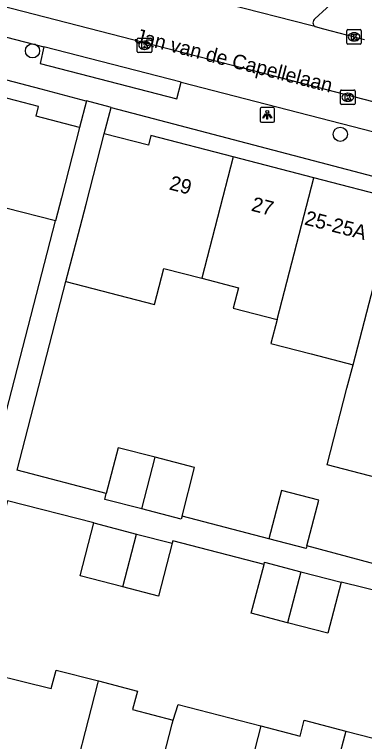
# Model space of a CAD drawing. Extents: x 163686 to 164493, y 382719 to 383870.
# Drawn here: x 164121.7 to 164145.7, y 383167.2 to 383217.3 of the extents above; entities that cross this region are included whole.
import ezdxf

# ---------------------------------------------------------------- set-up
doc = ezdxf.new("R2010")
doc.units = 0
for name, color, linetype in [('IMGEO_Boom', 7, 'Continuous'), ('IMGEO_Kolk', 7, 'Continuous'), ('IMGEO_Lichtpunt', 7, 'Continuous'), ('IMGEO_Openbare_ruimte_label', 7, 'Continuous'), ('IMGEO_Pand', 7, 'Continuous'), ('IMGEO_Pand_nummerreeks', 7, 'Continuous'), ('IMGEO_Rijbaan_lokaal_open', 7, 'Continuous'), ('IMGEO_Voetpad_open', 7, 'Continuous')]:
    doc.layers.add(name, color=color, linetype=linetype)

msp = doc.modelspace()

# ---------------------------------------------------------------- linework, layer by layer
at = {"layer": 'IMGEO_Boom'}
for centre in [(164122.893, 383214.805), (164144.081, 383209.057)]:
    msp.add_circle(centre, 0.489, dxfattribs=at)
at = {"layer": 'IMGEO_Kolk'}
for p, q in [((164144.528, 383215.338), (164144.528, 383216.19)), ((164144.603, 383216.264), (164145.455, 383216.264)), ((164145.529, 383216.19), (164145.529, 383215.338)), ((164130.182, 383215.685), (164131.034, 383215.685)), ((164145.016, 383216.044), (164145.041, 383216.044)), ((164130.107, 383214.759), (164130.107, 383215.611)), ((164130.595, 383215.465), (164130.62, 383215.465)), ((164131.108, 383215.611), (164131.108, 383214.759)), ((164145.455, 383215.264), (164144.603, 383215.264)), ((164145.039, 383215.484), (164145.014, 383215.484)), ((164131.034, 383214.685), (164130.182, 383214.685)), ((164130.618, 383214.905), (164130.593, 383214.905)), ((164144.094, 383211.181), (164144.094, 383212.033)), ((164144.169, 383212.107), (164145.021, 383212.107)), ((164144.582, 383211.887), (164144.607, 383211.887)), ((164145.095, 383212.033), (164145.095, 383211.181)), ((164144.605, 383211.327), (164144.58, 383211.327)), ((164145.021, 383211.107), (164144.169, 383211.107))]:
    msp.add_line(p, q, dxfattribs=at)
for points in [[(164144.528, 383215.338), (164144.528, 383216.19)], [(164144.603, 383216.264), (164145.455, 383216.264)], [(164145.529, 383216.19), (164145.529, 383215.338)], [(164130.182, 383215.685), (164131.034, 383215.685)], [(164144.849, 383215.964), (164144.972, 383215.964), (164144.972, 383215.813), (164145.102, 383215.964), (164145.266, 383215.964), (164145.12, 383215.813), (164145.273, 383215.564), (164145.121, 383215.564), (164145.036, 383215.728), (164144.972, 383215.661), (164144.972, 383215.564), (164144.849, 383215.564), (164144.849, 383215.964)], [(164130.107, 383214.759), (164130.107, 383215.611)], [(164130.428, 383215.385), (164130.551, 383215.385), (164130.551, 383215.234), (164130.681, 383215.385), (164130.845, 383215.385), (164130.699, 383215.234), (164130.852, 383214.985), (164130.7, 383214.985), (164130.615, 383215.149), (164130.551, 383215.082), (164130.551, 383214.985), (164130.428, 383214.985), (164130.428, 383215.385)], [(164131.108, 383215.611), (164131.108, 383214.759)], [(164145.455, 383215.264), (164144.603, 383215.264)], [(164131.034, 383214.685), (164130.182, 383214.685)], [(164144.094, 383211.181), (164144.094, 383212.033)], [(164144.169, 383212.107), (164145.021, 383212.107)], [(164144.415, 383211.807), (164144.538, 383211.807), (164144.538, 383211.656), (164144.668, 383211.807), (164144.832, 383211.807), (164144.686, 383211.656), (164144.839, 383211.407), (164144.687, 383211.407), (164144.602, 383211.571), (164144.538, 383211.504), (164144.538, 383211.407), (164144.415, 383211.407), (164144.415, 383211.807)], [(164145.095, 383212.033), (164145.095, 383211.181)], [(164145.021, 383211.107), (164144.169, 383211.107)]]:
    msp.add_lwpolyline(points, dxfattribs=at)
for centre, start, end in [((164144.605, 383216.188), 91.552, 178.448), ((164144.605, 383216.188), 91.552, 178.448), ((164145.453, 383216.188), 1.552, 88.448), ((164145.453, 383216.188), 1.552, 88.448), ((164130.184, 383215.609), 91.552, 178.448), ((164130.184, 383215.609), 91.552, 178.448), ((164131.032, 383215.609), 1.552, 88.448), ((164131.032, 383215.609), 1.552, 88.448), ((164144.605, 383215.34), 181.552, 268.448), ((164144.605, 383215.34), 181.552, 268.448), ((164145.453, 383215.34), 271.552, 358.448), ((164145.453, 383215.34), 271.552, 358.448), ((164130.184, 383214.761), 181.552, 268.448), ((164130.184, 383214.761), 181.552, 268.448), ((164131.032, 383214.761), 271.552, 358.448), ((164131.032, 383214.761), 271.552, 358.448), ((164144.171, 383212.031), 91.552, 178.448), ((164144.171, 383212.031), 91.552, 178.448), ((164145.019, 383212.031), 1.552, 88.448), ((164145.019, 383212.031), 1.552, 88.448), ((164144.171, 383211.183), 181.552, 268.448), ((164144.171, 383211.183), 181.552, 268.448), ((164145.019, 383211.183), 271.552, 358.448), ((164145.019, 383211.183), 271.552, 358.448)]:
    msp.add_arc(centre, 0.0765, start, end, dxfattribs=at)
for centre, major_axis, ratio, start_param, end_param in [((164145.015, 383215.764), (-0.387, 0.002), 0.722429, 4.712389, 7.853982), ((164145.04, 383215.764), (-0.39, 0.002), 0.717154, 1.570796, 4.712389), ((164130.594, 383215.185), (-0.387, 0.002), 0.722429, 4.712389, 7.853982), ((164130.619, 383215.185), (-0.39, 0.002), 0.717154, 1.570796, 4.712389), ((164144.581, 383211.607), (-0.387, 0.002), 0.722429, 4.712389, 7.853982), ((164144.606, 383211.607), (-0.39, 0.002), 0.717154, 1.570796, 4.712389)]:
    msp.add_ellipse(centre, major_axis=major_axis, ratio=ratio, start_param=start_param, end_param=end_param, dxfattribs=at)
at = {"layer": 'IMGEO_Lichtpunt'}
for p, q in [((164138.558, 383210.8), (164138.558, 383209.993)), ((164138.558, 383210.8), (164138.558, 383209.993)), ((164139.46, 383210.895), (164138.652, 383210.895)), ((164139.46, 383210.895), (164138.652, 383210.895)), ((164139.554, 383209.993), (164139.554, 383210.8)), ((164139.554, 383209.993), (164139.554, 383210.8)), ((164138.652, 383209.899), (164139.46, 383209.899)), ((164138.652, 383209.899), (164139.46, 383209.899))]:
    msp.add_line(p, q, dxfattribs=at)
for points in [[(164138.932, 383210.464), (164138.971, 383210.436), (164138.783, 383210.174), (164138.745, 383210.201), (164138.932, 383210.464)], [(164139.034, 383210.416), (164139.081, 383210.416), (164139.081, 383210.094), (164139.034, 383210.094), (164139.034, 383210.416)], [(164139.144, 383210.436), (164139.182, 383210.463), (164139.369, 383210.201), (164139.33, 383210.173), (164139.144, 383210.436)]]:
    msp.add_lwpolyline(points, dxfattribs=at)
msp.add_circle((164139.057, 383210.598), 0.0994, dxfattribs=at)
for centre, start, end in [((164138.652, 383210.8), 90, 180), ((164138.652, 383210.8), 90, 180), ((164139.46, 383210.8), 0, 90), ((164139.46, 383210.8), 0, 90), ((164138.652, 383209.993), 180, 270), ((164138.652, 383209.993), 180, 270), ((164139.46, 383209.993), 270, 0), ((164139.46, 383209.993), 270, 360)]:
    msp.add_arc(centre, 0.0946, start, end, dxfattribs=at)
at = {"layer": 'IMGEO_Pand'}
for points in [[(164126.14, 383209.527), (164123.14, 383210.305), (164123.312, 383210.967), (164117.47, 383212.48)], [(164126.14, 383209.527), (164124.885, 383204.688), (164124.471, 383203.091)], [(164125.201, 383198.919), (164126.168, 383202.651), (164126.583, 383204.249), (164127.838, 383209.088)], [(164136.711, 383207.499), (164131.051, 383208.967), (164130.878, 383208.299), (164127.838, 383209.088)], [(164136.711, 383207.499), (164134.545, 383199.144)], [(164142.264, 383206.059), (164136.711, 383207.499)], [(164139.734, 383196.302), (164142.264, 383206.059)], [(164147.926, 383204.591), (164142.264, 383206.059)], [(164144.962, 383193.187), (164147.926, 383204.591)], [(164124.471, 383203.091), (164121.059, 383203.975), (164120.74, 383202.742), (164118.128, 383203.418), (164115.309, 383204.148)], [(164125.201, 383198.919), (164131.295, 383197.338), (164131.939, 383199.82), (164134.545, 383199.144)], [(164134.545, 383199.144), (164137.065, 383198.491), (164136.702, 383197.088), (164139.734, 383196.302)], [(164139.734, 383196.302), (164139.307, 383194.654), (164142.074, 383193.936), (164144.962, 383193.187)], [(164150.779, 383192.563), (164150.549, 383191.667), (164148.385, 383192.228), (164146.613, 383185.394), (164143.169, 383186.287), (164144.541, 383191.566), (164144.962, 383193.187)], [(164131.343, 383186.81), (164128.79, 383187.469), (164127.975, 383184.316)], [(164130.425, 383183.253), (164131.343, 383186.81)], [(164133.188, 383182.758), (164134.054, 383186.11), (164131.343, 383186.81)], [(164130.425, 383183.253), (164127.871, 383183.912), (164127.975, 383184.316)], [(164141.783, 383180.711), (164142.605, 383183.861), (164140.027, 383184.533), (164139.159, 383181.203)], [(164133.188, 383182.758), (164133.135, 383182.553), (164130.425, 383183.253)], [(164129.119, 383177.882), (164126.172, 383178.643), (164127.113, 383182.288)], [(164127.113, 383182.288), (164130.06, 383181.527)], [(164129.119, 383177.882), (164130.06, 383181.527)], [(164130.06, 383181.527), (164132.513, 383180.894)], [(164141.783, 383180.711), (164141.736, 383180.531), (164139.159, 383181.203)], [(164132.513, 383180.894), (164131.572, 383177.249), (164129.119, 383177.882)], [(164140.455, 383175.418), (164137.958, 383176.069), (164138.832, 383179.422)], [(164138.832, 383179.422), (164138.875, 383179.586), (164141.372, 383178.934)], [(164141.372, 383178.934), (164140.455, 383175.418)], [(164141.372, 383178.934), (164144.147, 383178.21)], [(164144.147, 383178.21), (164143.23, 383174.694), (164140.455, 383175.418)], [(164118.218, 383172.36), (164124.19, 383170.881), (164124.521, 383172.163), (164127.447, 383171.406)], [(164125.256, 383162.914), (164127.401, 383171.225), (164127.447, 383171.406)], [(164127.447, 383171.406), (164130.113, 383170.716), (164129.782, 383169.439), (164132.583, 383168.714)], [(164132.583, 383168.714), (164132.93, 383169.785), (164138.622, 383168.313)], [(164130.721, 383161.5), (164132.516, 383168.457), (164132.583, 383168.714)], [(164138.622, 383168.313), (164141.324, 383167.614), (164141.605, 383168.701), (164144.459, 383167.962)], [(164138.622, 383168.313), (164136.48, 383160.01)], [(164144.459, 383167.962), (164143.901, 383165.802), (164143.833, 383165.537), (164142.036, 383158.573)], [(164144.459, 383167.962), (164147.232, 383167.244), (164146.965, 383166.213), (164149.824, 383165.473)]]:
    msp.add_lwpolyline(points, dxfattribs=at)
at = {"layer": 'IMGEO_Rijbaan_lokaal_open'}
for points in [[(164065.47, 383232.191), (164137.37, 383213.628), (164191.674, 383199.573)], [(164067.443, 383229.643), (164078.076, 383226.898), (164083.857, 383225.406), (164123.682, 383215.09)], [(164142.358, 383216.47), (164142.06, 383216.549), (164130.537, 383219.506), (164130.19, 383219.614)], [(164142.358, 383216.47), (164142.92, 383216.322), (164145.029, 383215.764), (164145.758, 383215.595)], [(164133.127, 383212.643), (164123.682, 383215.09)], [(164133.127, 383212.643), (164172.83, 383202.406)]]:
    msp.add_lwpolyline(points, dxfattribs=at)
at = {"layer": 'IMGEO_Voetpad_open'}
for points in [[(164089.752, 383221.038), (164123.472, 383212.179), (164126.574, 383211.363), (164126.62, 383211.351)], [(164145.544, 383219.979), (164142.339, 383217.007)], [(164123.682, 383215.09), (164123.423, 383213.922), (164132.837, 383211.498), (164133.127, 383212.643)], [(164126.62, 383211.351), (164126.14, 383209.527)], [(164128.316, 383210.906), (164128.252, 383210.923), (164126.62, 383211.351)], [(164127.838, 383209.088), (164128.316, 383210.906)], [(164128.316, 383210.906), (164131.207, 383210.146), (164165.211, 383201.212)], [(164114.311, 383187.86), (164120.15, 383186.353), (164124.471, 383203.091)], [(164127.975, 383184.316), (164121.844, 383185.915), (164125.201, 383198.919)], [(164127.113, 383182.288), (164121.18, 383183.82), (164118.218, 383172.36)], [(164139.159, 383181.203), (164133.188, 383182.758)], [(164138.832, 383179.422), (164132.558, 383181.059), (164132.513, 383180.894)], [(164150.841, 383178.278), (164141.783, 383180.711)], [(164150.374, 383176.667), (164144.147, 383178.21)]]:
    msp.add_lwpolyline(points, dxfattribs=at)
msp.add_arc((164142.516, 383216.744), 0.317, 123.9754, 240.0773, dxfattribs=at)

# ---------------------------------------------------------------- texts
at = {"layer": 'IMGEO_Openbare_ruimte_label'}
msp.add_text('Jan van de Capellelaan', height=1, rotation=345.5745, dxfattribs=at).set_placement((164129.858, 383215.397))
at = {"layer": 'IMGEO_Pand_nummerreeks'}
for s, rotation, p in [('29', 345.4621, (164132.252, 383205.267)), ('27', 345.4621, (164137.901, 383203.803)), ('25-25A', 345.4655, (164141.562, 383202.853))]:
    msp.add_text(s, height=1, rotation=rotation, dxfattribs=at).set_placement(p)

doc.saveas('drawing.dxf')
